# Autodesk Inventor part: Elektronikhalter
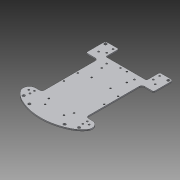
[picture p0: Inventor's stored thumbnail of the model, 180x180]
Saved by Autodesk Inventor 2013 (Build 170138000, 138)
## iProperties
Created: 2012-08
Part Number: Elektronikhalter
Material: Aluminium 6061
Document SubType Name: Modeling
Designer: rYan
Mass: 60.9181 g
Surface Area: 243.074 cm^2
Volume: 22.479 cm^3
Density: 2.71 g/cm^3
Author: rYan
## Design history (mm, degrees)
sketch "Skizze1" dims "d122" = 174
  geometry: L1 (-53.75, 66)-(-53.75, 40.75); L2 (-51.75, 38.75)-(-39, 38.75); L3 (-35, 34.75)-(-35, -46); L4 (35, -46)-(35, 34.75); L5 (39, 38.75)-(51.75, 38.75); L6 (53.75, 40.75)-(53.75, 66); L7 (0, 121.8)-(0, -121.8) reference; L8 (-121.8, 0)-(121.8, 0) reference; L9 (-45.095, -50)-(-39, -50); L10 (45.095, -50)-(39, -50); L11 (-32.5, 67.75)-(-32.5, 50.75); L12 (32.5, 67.75)-(32.5, 50.75); L13 (-30.5, 48.75)-(30.5, 48.75); L14 (50, 69.75)-(34.5, 69.75); L15 (-34.5, 69.75)-(-50, 69.75); A1 r 3.75 centre (50, 66) between (53.75, 66) and (50, 69.75); A2 r 3.75 centre (-50, 66) between (-50, 69.75) and (-53.75, 66); A3 r 2 centre (-30.5, 50.75) between (-32.5, 50.75) and (-30.5, 48.75); A4 r 2 centre (30.5, 50.75) between (30.5, 48.75) and (32.5, 50.75); A5 r 2 centre (-34.5, 67.75) between (-32.5, 67.75) and (-34.5, 69.75); A6 r 2 centre (34.5, 67.75) between (34.5, 69.75) and (32.5, 67.75); A7 r 4 centre (-39, 34.75) between (-35, 34.75) and (-39, 38.75); A8 r 4 centre (39, 34.75) between (39, 38.75) and (35, 34.75); A9 r 4 centre (-39, -46) between (-39, -50) and (-35, -46); A10 r 4 centre (39, -46) between (35, -46) and (39, -50); A11 r 2 centre (-51.75, 40.75) between (-53.75, 40.75) and (-51.75, 38.75); A12 r 2 centre (51.75, 40.75) between (51.75, 38.75) and (53.75, 40.75); A13 r 10 centre (-45.095, -60) between (-45.095, -50) and (-53.095, -66); A14 r 10 centre (45.095, -60) between (53.095, -66) and (45.095, -50); A15 r 40 centre (-21.095, -42) between (-53.095, -66) and (-39.048, -77.745); A16 r 40 centre (21.095, -42) between (39.048, -77.745) and (53.095, -66); A17 r 87 centre (0, 0) between (-39.048, -77.745) and (39.048, -77.745); 2 further points
  constraints: 34 point on circle, 31 tangent, 26 end point, 17 centre point, 6 parallel, 5 perpendicular, 2 coincident, 1 collinear, 1 symmetric about line, 1 vertical, 15 other
  dimensions: "d24" = 7.5 diameter of A1; "d25" = 7.5 diameter of A2; "d26" = 100 distance of L14.start L15.end; "d27" = 66 distance from line of L8 L6.end; "d44" = 70 distance between parallel lines of L4 L3; "d55" = 2 radius of A5; "d56" = 2 radius of A3; "d58" = 31 distance between parallel lines of L5 L14; "d59" = 10 distance between parallel lines of L13 L5; "d60" = 65 distance between parallel lines of L11 L12; "d61" = 4 radius of A7; "d95" = 4 radius of A9; "d96" = 2 radius of A11; "d97" = 10 radius of A13; "d123" = 40 radius of A15; "d154" = 88.75 distance between parallel lines of L2 L9; "d155" = 42.19005 distance of A16.centre A15.centre
extrude "Extrusion1" new body sketch "Skizze1" distance "d5" = 2; taper "d6" = 0 deg
node "Spiegelebene"
sketch "Skizze2"
  geometry: L1 (0, 101.1)-(0, -118.35) reference; L2 (-77.133, 0)-(77.133, 0) reference; 3 further points
  dimensions: "d7" = 50 distance from line of point (50, 66) L1; "d8" = 66 distance from line of L2 point (50, 66); "d9" = 28 distance from line of point (28, -77) L1; "d10" = 77 distance from line of L2 point (28, -77)
hole "Montagestreben" sketch "Skizze2" at (50, 66), (28, -77) diameter "d11" = 4.2; stored, may be unused: countersink angle "d15" = 90 deg, drill point angle "d17" = 118 deg; dims "d12" = 6, "d13" = 4, "d14" = 2, "d16" = 8
sketch "Skizze3"
  geometry: L1 (-77.133, 0)-(77.133, 0) reference; L2 (0, 101.1)-(0, -118.35) reference; L3 (32, 4)-(32, -18); 4 further points; 1 other entity
  constraints: 2 end point, 1 vertical, 1 other
  dimensions: "d30" = 22 distance of L3.end L3.start; "d33" = 3 dimension on L3.start; "d34" = 4 distance from line of L3.start L1
hole "Kondensatorhalter" sketch "Skizze3" at (32, 4), (32, -18) diameter "d35" = 2.459; stored, may be unused: countersink angle "d39" = 90 deg, drill point angle "d41" = 118 deg; dims "d36" = 6, "d37" = 4, "d38" = 2, "d40" = 8
sketch "Skizze4"
  geometry: L1 (0, 101.1)-(0, -118.35) reference; L2 (-77.133, 0)-(77.133, 0) reference; 2 further points
  dimensions: "d46" = 40 distance from line of point (22, 40) L2; "d47" = 22 distance from line of L1 point (22, 40)
hole "Akku Anschlag" sketch "Skizze4" at (22, 40) diameter "d48" = 2.7; stored, may be unused: countersink angle "d52" = 90 deg, drill point angle "d54" = 118 deg; dims "d49" = 6, "d50" = 4, "d51" = 2, "d53" = 8
sketch "Skizze5"
  geometry: L1 (0, 101.1)-(0, -118.35) reference; L2 (-77.133, 0)-(77.133, 0) reference; 7 further points
  dimensions: "d64" = 37 distance from line of point (37, 65) L1; "d65" = 65 distance from line of L2 point (37, 65); "d73" = 62 distance from line of L2 point (42, -62); "d74" = 42 distance from line of L1 point (42, -62); "d133" = 37 distance from line of point (37, 55) L1; "d134" = 45 distance from line of point (45, 50) L1; "d135" = 55 distance from line of point (37, 55) L2; "d136" = 50 distance from line of L2 point (45, 50); "d137" = 42 distance from line of point (42, -55) L1; "d138" = 48 distance from line of point (48, -58) L1; "d139" = 55 distance from line of point (42, -55) L2; "d140" = 58 distance from line of L2 point (48, -58)
hole "Mainboardstreben" sketch "Skizze5" at (37, 65), (42, -62), (37, 55), (45, 50), (42, -55), (48, -58) diameter "d66" = 2.7; stored, may be unused: countersink angle "d70" = 90 deg, drill point angle "d72" = 118 deg; dims "d67" = 6, "d68" = 4, "d69" = 2, "d71" = 8
sketch "Skizze7"
  geometry: L1 (0, 101.1)-(0, -118.35) reference; L2 (-77.133, 0)-(77.133, 0) reference; 2 further points
  dimensions: "d86" = 5 distance from line of point (5, 45) L1; "d87" = 45 distance from line of L2 point (5, 45)
hole "Ball Detection Halter" sketch "Skizze7" at (5, 45) diameter "d88" = 2.459; stored, may be unused: countersink angle "d92" = 90 deg, drill point angle "d94" = 118 deg; dims "d89" = 6, "d90" = 4, "d91" = 2, "d93" = 8
sketch "Skizze9"
  geometry: L1 (0, 101.1)-(0, -118.35) reference; L2 (-77.133, 0)-(77.133, 0) reference; 2 further points
  dimensions: "d124" = 70 distance from line of point (44, -70) L2; "d125" = 44 distance from line of L1 point (44, -70)
hole "Ringhalter" sketch "Skizze9" at (44, -70) diameter "d126" = 4.2; stored, may be unused: countersink angle "d130" = 90 deg, drill point angle "d132" = 118 deg; dims "d127" = 6, "d128" = 4, "d129" = 2, "d131" = 8
sketch "Skizze8"
  geometry: L1 (-77.133, 0)-(77.133, 0) reference; L2 (0, 101.1)-(0, -118.35) reference; L3 (15, -65)-(15, 9); L4 (20, -54)-(20, 30); 2 further points
  constraints: 4 end point, 1 coincident, 1 parallel
  dimensions: "d111" = 84 distance of L4.end L4.start; "d116" = 9 distance from line of L1 point (15, 9); "d142" = 15 distance between parallel lines of L2 L3; "d143" = 74 distance of point (15, 9) L3.start; "d144" = 20 distance between parallel lines of L4 L2; "d145" = 30 distance from line of L4.end L1
hole "Kickeroptionen" sketch "Skizze8" at (20, -54), (20, 30), (15, 9), (15, -65) diameter "d102" = 2.459; stored, may be unused: countersink angle "d106" = 90 deg, drill point angle "d108" = 118 deg; dims "d103" = 6, "d104" = 4, "d105" = 2, "d107" = 8
mirror "Spiegeln1"
node "Volumenkörper1"
